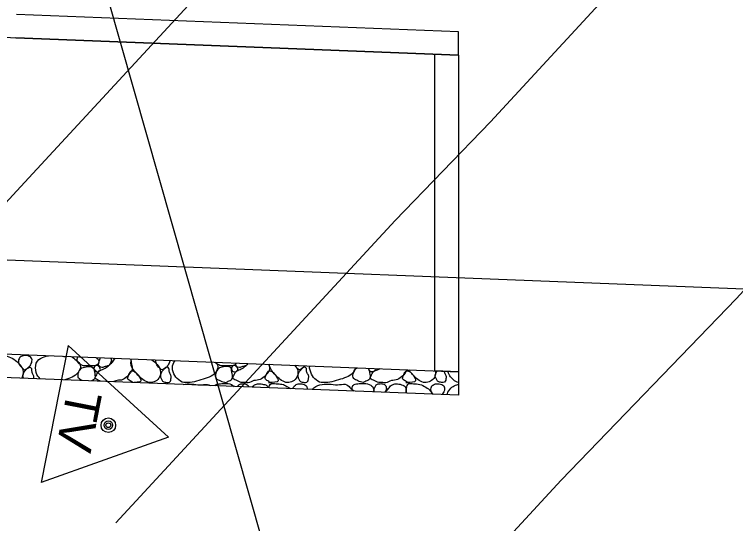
# Model space of a CAD drawing. Extents: x 1385284 to 1385995, y 1975154 to 1975620.
# Drawn here: x 1385575.03 to 1385605.82, y 1975429.75 to 1975451.48 of the extents above; entities that cross this region are included whole.
import ezdxf

# ---------------------------------------------------------------- set-up
doc = ezdxf.new("R2010")
doc.units = 0
for name, color, linetype in [('Default', 7, 'Continuous'), ('DTM CONTOURS_MAJOR', 7, 'Continuous'), ('DTM_CONTOURS_MINOR', 7, 'Continuous'), ('R_Proposed Const Limits', 7, 'Continuous'), ('R_Proposed Road', 7, 'Continuous'), ('S_SECONDARY_CTL', 7, 'Continuous')]:
    doc.layers.add(name, color=color, linetype=linetype)

msp = doc.modelspace()

# ---------------------------------------------------------------- linework, layer by layer
at = {"layer": 'Default'}
for p, q in [((1385568.987, 1975487.408), (1385600.804, 1975375.659)), ((1385593.986, 1975450.744), (1385575.124, 1975451.48)), ((1385593.986, 1975449.744), (1385593.986, 1975450.744)), ((1385593.986, 1975449.744), (1385575.085, 1975450.481)), ((1385575.085, 1975450.481), (1385593.986, 1975449.744)), ((1385592.986, 1975436.272), (1385592.986, 1975449.782)), ((1385592.986, 1975449.782), (1385593.986, 1975449.744)), ((1385593.986, 1975449.744), (1385593.986, 1975436.233)), ((1385574.559, 1975436.991), (1385593.986, 1975436.233)), ((1385592.986, 1975436.272), (1385593.986, 1975436.233)), ((1385593.986, 1975436.233), (1385592.986, 1975436.272)), ((1385593.986, 1975436.233), (1385593.986, 1975435.233)), ((1385593.986, 1975435.233), (1385574.52, 1975435.992))]:
    msp.add_line(p, q, dxfattribs=at)
msp.add_arc((1385575.884, 1975470.965), 20.5, 145.4884, 267.767, dxfattribs=at)
for points in [[(1385574.541, 1975435.991), (1385574.531, 1975436.001), (1385574.44, 1975436.091), (1385574.28, 1975436.257), (1385574.122, 1975436.498), (1385574.154, 1975436.724), (1385574.225, 1975436.966), (1385574.454, 1975436.913), (1385574.724, 1975436.919), (1385575.013, 1975436.774), (1385575.27, 1975436.563), (1385575.418, 1975436.303), (1385575.404, 1975436.06), (1385575.351, 1975435.979), (1385575.336, 1975435.96)], [(1385575.519, 1975436.344), (1385575.488, 1975436.27), (1385575.283, 1975436.452), (1385575.181, 1975436.63), (1385575.232, 1975436.85), (1385575.396, 1975436.923), (1385575.623, 1975436.93), (1385575.813, 1975436.805), (1385575.761, 1975436.567), (1385575.648, 1975436.402), (1385575.545, 1975436.355), (1385575.519, 1975436.344)], [(1385576.129, 1975435.929), (1385576.069, 1975435.99), (1385575.929, 1975436.165), (1385575.91, 1975436.641), (1385576.23, 1975436.871), (1385576.441, 1975436.91), (1385576.491, 1975436.915)], [(1385577.11, 1975436.891), (1385577.13, 1975436.89), (1385577.164, 1975436.887), (1385577.199, 1975436.887), (1385577.214, 1975436.887)], [(1385577.462, 1975436.878), (1385577.528, 1975436.853), (1385577.663, 1975436.729), (1385577.905, 1975436.536), (1385577.78, 1975436.176), (1385577.506, 1975435.992), (1385577.31, 1975435.925), (1385577.177, 1975435.888)], [(1385578.073, 1975436.49), (1385578.018, 1975436.467), (1385577.873, 1975436.524), (1385577.711, 1975436.611), (1385577.7, 1975436.767), (1385577.733, 1975436.841), (1385577.757, 1975436.866)], [(1385578.511, 1975436.837), (1385578.533, 1975436.82), (1385578.617, 1975436.757), (1385578.655, 1975436.649), (1385578.559, 1975436.482), (1385578.353, 1975436.49), (1385578.193, 1975436.484), (1385578.073, 1975436.49)], [(1385578.71, 1975435.828), (1385578.701, 1975435.833), (1385578.622, 1975435.877), (1385578.435, 1975435.935), (1385578.549, 1975436.104), (1385578.628, 1975436.29), (1385578.853, 1975436.335), (1385579.053, 1975436.493), (1385579.229, 1975436.634), (1385579.286, 1975436.762), (1385579.326, 1975436.805)], [(1385579.045, 1975436.49), (1385578.997, 1975436.476), (1385578.901, 1975436.452), (1385578.766, 1975436.399), (1385578.64, 1975436.44), (1385578.613, 1975436.547), (1385578.643, 1975436.661), (1385578.677, 1975436.762), (1385578.698, 1975436.813), (1385578.707, 1975436.829)], [(1385579.154, 1975436.812), (1385579.181, 1975436.756), (1385579.158, 1975436.637), (1385579.097, 1975436.52), (1385579.045, 1975436.49)], [(1385579.988, 1975436.779), (1385580.009, 1975436.721), (1385580.018, 1975436.568), (1385580.096, 1975436.284), (1385579.882, 1975436.076), (1385579.66, 1975435.854), (1385579.417, 1975435.882), (1385579.275, 1975435.82), (1385579.246, 1975435.807)], [(1385580.811, 1975435.77), (1385580.739, 1975435.767), (1385580.557, 1975435.852), (1385580.36, 1975436.034), (1385580.15, 1975436.257), (1385579.991, 1975436.498), (1385580.011, 1975436.684), (1385580.023, 1975436.765), (1385580.026, 1975436.778)], [(1385580.903, 1975436.743), (1385580.976, 1975436.693), (1385581.148, 1975436.543), (1385581.288, 1975436.303), (1385581.25, 1975435.986), (1385581.064, 1975435.814), (1385580.895, 1975435.77), (1385580.811, 1975435.77)], [(1385581.388, 1975436.344), (1385581.357, 1975436.27), (1385581.152, 1975436.452), (1385581.065, 1975436.612), (1385581.061, 1975436.714), (1385581.065, 1975436.737)], [(1385581.665, 1975436.714), (1385581.67, 1975436.675), (1385581.618, 1975436.549), (1385581.518, 1975436.402), (1385581.414, 1975436.355), (1385581.388, 1975436.344)], [(1385582.315, 1975435.774), (1385582.247, 1975435.74), (1385582.024, 1975435.878), (1385581.809, 1975436.123), (1385581.737, 1975436.512), (1385581.869, 1975436.673), (1385581.899, 1975436.705)], [(1385575.424, 1975435.956), (1385575.413, 1975435.978), (1385575.376, 1975436.038), (1385575.413, 1975436.183), (1385575.507, 1975436.295), (1385575.584, 1975436.384), (1385575.664, 1975436.44), (1385575.789, 1975436.388), (1385575.746, 1975436.271), (1385575.808, 1975436.146), (1385575.856, 1975436.024), (1385575.846, 1975435.955), (1385575.843, 1975435.94)], [(1385577.926, 1975435.859), (1385577.875, 1975435.881), (1385577.738, 1975435.937), (1385577.741, 1975436.149), (1385577.852, 1975436.394), (1385578.067, 1975436.444), (1385578.429, 1975436.473), (1385578.432, 1975436.232), (1385578.514, 1975435.921), (1385578.38, 1975435.869), (1385578.327, 1975435.843)], [(1385578.617, 1975436.224), (1385578.58, 1975436.225), (1385578.495, 1975436.222), (1385578.415, 1975436.304), (1385578.424, 1975436.422), (1385578.508, 1975436.524), (1385578.635, 1975436.474), (1385578.738, 1975436.313), (1385578.651, 1975436.254), (1385578.617, 1975436.224)], [(1385581.715, 1975435.875), (1385581.704, 1975435.851), (1385581.656, 1975435.761), (1385581.534, 1975435.775), (1385581.355, 1975435.794), (1385581.317, 1975435.911), (1385581.243, 1975436.019), (1385581.282, 1975436.183), (1385581.377, 1975436.295), (1385581.454, 1975436.384), (1385581.533, 1975436.44), (1385581.658, 1975436.388), (1385581.615, 1975436.271), (1385581.677, 1975436.146), (1385581.759, 1975436.009), (1385581.696, 1975435.906), (1385581.715, 1975435.875)], [(1385583.611, 1975436.638), (1385583.641, 1975436.602), (1385583.758, 1975436.477), (1385583.649, 1975436.176), (1385583.36, 1975435.986), (1385582.992, 1975435.885), (1385582.621, 1975435.757), (1385582.388, 1975435.771), (1385582.315, 1975435.774)], [(1385583.943, 1975436.49), (1385583.887, 1975436.467), (1385583.747, 1975436.523), (1385583.651, 1975436.585), (1385583.609, 1975436.638)], [(1385584.048, 1975435.77), (1385583.976, 1975435.781), (1385583.831, 1975435.85), (1385583.608, 1975435.92), (1385583.611, 1975436.149), (1385583.721, 1975436.394), (1385583.937, 1975436.444), (1385584.298, 1975436.473), (1385584.301, 1975436.232), (1385584.383, 1975435.92), (1385584.199, 1975435.843), (1385584.096, 1975435.795), (1385584.048, 1975435.77)], [(1385584.501, 1975436.603), (1385584.491, 1975436.562), (1385584.427, 1975436.482), (1385584.223, 1975436.49), (1385584.063, 1975436.484), (1385583.943, 1975436.49)], [(1385584.486, 1975436.224), (1385584.449, 1975436.225), (1385584.364, 1975436.222), (1385584.285, 1975436.304), (1385584.293, 1975436.422), (1385584.377, 1975436.524), (1385584.504, 1975436.474), (1385584.608, 1975436.313), (1385584.52, 1975436.254), (1385584.486, 1975436.224)], [(1385584.771, 1975435.77), (1385584.7, 1975435.766), (1385584.564, 1975435.846), (1385584.305, 1975435.935), (1385584.419, 1975436.104), (1385584.498, 1975436.29), (1385584.722, 1975436.335), (1385584.891, 1975436.467), (1385584.978, 1975436.552), (1385585.01, 1975436.583)], [(1385584.914, 1975436.49), (1385584.867, 1975436.476), (1385584.771, 1975436.452), (1385584.636, 1975436.399), (1385584.509, 1975436.44), (1385584.481, 1975436.525), (1385584.491, 1975436.577), (1385584.497, 1975436.603)], [(1385585.899, 1975436.549), (1385585.915, 1975436.47), (1385585.952, 1975436.271), (1385585.751, 1975436.076), (1385585.529, 1975435.854), (1385585.253, 1975435.887), (1385585.016, 1975435.711), (1385584.85, 1975435.791), (1385584.771, 1975435.77)], [(1385584.998, 1975436.584), (1385584.977, 1975436.546), (1385584.951, 1975436.511), (1385584.914, 1975436.49)], [(1385586.68, 1975435.77), (1385586.609, 1975435.767), (1385586.426, 1975435.852), (1385586.229, 1975436.034), (1385586.019, 1975436.257), (1385585.922, 1975436.447), (1385585.89, 1975436.546), (1385585.889, 1975436.549)], [(1385587.011, 1975436.505), (1385587.07, 1975436.42), (1385587.156, 1975436.279), (1385587.119, 1975435.986), (1385586.933, 1975435.814), (1385586.765, 1975435.77), (1385586.68, 1975435.77)], [(1385587.258, 1975436.344), (1385587.226, 1975436.27), (1385587.078, 1975436.399), (1385587.014, 1975436.488), (1385587.002, 1975436.506)], [(1385587.584, 1975435.875), (1385587.574, 1975435.851), (1385587.525, 1975435.761), (1385587.403, 1975435.775), (1385587.224, 1975435.794), (1385587.187, 1975435.911), (1385587.112, 1975436.019), (1385587.151, 1975436.183), (1385587.246, 1975436.295), (1385587.323, 1975436.384), (1385587.403, 1975436.44), (1385587.527, 1975436.388), (1385587.485, 1975436.271), (1385587.546, 1975436.146), (1385587.629, 1975436.009), (1385587.565, 1975435.906), (1385587.584, 1975435.875)], [(1385587.438, 1975436.489), (1385587.407, 1975436.449), (1385587.348, 1975436.385), (1385587.283, 1975436.355), (1385587.258, 1975436.344)], [(1385588.184, 1975435.774), (1385588.117, 1975435.74), (1385587.894, 1975435.878), (1385587.706, 1975436.096), (1385587.621, 1975436.364), (1385587.639, 1975436.481)], [(1385589.58, 1975436.405), (1385589.576, 1975436.319), (1385589.488, 1975436.149), (1385589.23, 1975435.986), (1385588.861, 1975435.885), (1385588.49, 1975435.757), (1385588.257, 1975435.771), (1385588.184, 1975435.774)], [(1385589.917, 1975435.77), (1385589.845, 1975435.781), (1385589.701, 1975435.85), (1385589.477, 1975435.92), (1385589.48, 1975436.149), (1385589.551, 1975436.322), (1385589.646, 1975436.387), (1385589.673, 1975436.401)], [(1385590.15, 1975436.383), (1385590.181, 1975436.327), (1385590.188, 1975436.197), (1385590.252, 1975435.92), (1385590.068, 1975435.843), (1385589.965, 1975435.795), (1385589.917, 1975435.77)], [(1385590.356, 1975436.224), (1385590.318, 1975436.225), (1385590.234, 1975436.222), (1385590.166, 1975436.296), (1385590.156, 1975436.358), (1385590.159, 1975436.383)], [(1385590.641, 1975435.77), (1385590.569, 1975435.766), (1385590.434, 1975435.846), (1385590.174, 1975435.935), (1385590.288, 1975436.104), (1385590.367, 1975436.29), (1385590.539, 1975436.296), (1385590.621, 1975436.358), (1385590.629, 1975436.364)], [(1385590.46, 1975436.371), (1385590.473, 1975436.348), (1385590.451, 1975436.295), (1385590.389, 1975436.254), (1385590.356, 1975436.224)], [(1385580.1, 1975435.774), (1385580.061, 1975435.784), (1385579.975, 1975435.849), (1385579.822, 1975435.935), (1385579.931, 1975436.121), (1385579.979, 1975436.285), (1385580.16, 1975436.259), (1385580.28, 1975436.155), (1385580.347, 1975436.01), (1385580.519, 1975435.773), (1385580.188, 1975435.778), (1385580.138, 1975435.773)], [(1385585.998, 1975435.77), (1385585.95, 1975435.77), (1385585.854, 1975435.842), (1385585.691, 1975435.935), (1385585.8, 1975436.121), (1385585.848, 1975436.285), (1385586.029, 1975436.259), (1385586.149, 1975436.155), (1385586.216, 1975436.01), (1385586.403, 1975435.762), (1385585.653, 1975435.779), (1385586.04, 1975435.768), (1385586.031, 1975435.77)], [(1385591.785, 1975436.319), (1385591.785, 1975436.317), (1385591.763, 1975436.215), (1385591.62, 1975436.076), (1385591.398, 1975435.854), (1385591.122, 1975435.887), (1385590.885, 1975435.711), (1385590.72, 1975435.791), (1385590.641, 1975435.77)], [(1385591.867, 1975435.77), (1385591.819, 1975435.77), (1385591.723, 1975435.842), (1385591.561, 1975435.935), (1385591.67, 1975436.121), (1385591.717, 1975436.285), (1385591.899, 1975436.259), (1385592.018, 1975436.155), (1385592.085, 1975436.01), (1385592.272, 1975435.762), (1385591.523, 1975435.779), (1385591.909, 1975435.768), (1385591.901, 1975435.77)], [(1385592.549, 1975435.77), (1385592.478, 1975435.767), (1385592.295, 1975435.852), (1385592.099, 1975436.034), (1385591.955, 1975436.195), (1385591.88, 1975436.301), (1385591.871, 1975436.316)], [(1385592.992, 1975436.272), (1385592.996, 1975436.26), (1385593.023, 1975436.183), (1385592.988, 1975435.986), (1385592.802, 1975435.814), (1385592.634, 1975435.77), (1385592.549, 1975435.77)], [(1385593.453, 1975435.875), (1385593.443, 1975435.851), (1385593.395, 1975435.761), (1385593.272, 1975435.775), (1385593.094, 1975435.794), (1385593.056, 1975435.911), (1385592.982, 1975436.019), (1385593.012, 1975436.164), (1385593.064, 1975436.236), (1385593.091, 1975436.268)], [(1385593.365, 1975436.258), (1385593.383, 1975436.216), (1385593.42, 1975436.127), (1385593.498, 1975436.009), (1385593.434, 1975435.906), (1385593.453, 1975435.875)], [(1385593.986, 1975435.766), (1385593.93, 1975435.775), (1385593.749, 1975435.896), (1385593.621, 1975436.051), (1385593.549, 1975436.208), (1385593.535, 1975436.251)], [(1385583.606, 1975435.637), (1385583.618, 1975435.656), (1385583.669, 1975435.706), (1385583.866, 1975435.724), (1385584.151, 1975435.752), (1385584.345, 1975435.667), (1385584.414, 1975435.606)], [(1385585.89, 1975435.548), (1385585.9, 1975435.607), (1385585.967, 1975435.762), (1385586.193, 1975435.71), (1385586.463, 1975435.716), (1385586.676, 1975435.607), (1385586.782, 1975435.535), (1385586.811, 1975435.512)], [(1385589.503, 1975435.407), (1385589.492, 1975435.419), (1385589.444, 1975435.466), (1385589.439, 1975435.574), (1385589.516, 1975435.706), (1385589.736, 1975435.724), (1385590.035, 1975435.754), (1385590.334, 1975435.632), (1385590.385, 1975435.455), (1385590.366, 1975435.384), (1385590.362, 1975435.374)], [(1385591.768, 1975435.319), (1385591.766, 1975435.325), (1385591.739, 1975435.394), (1385591.762, 1975435.521), (1385591.833, 1975435.763), (1385592.062, 1975435.71), (1385592.332, 1975435.716), (1385592.621, 1975435.571), (1385592.794, 1975435.426), (1385592.881, 1975435.304), (1385592.899, 1975435.275)], [(1385582.234, 1975435.691), (1385582.334, 1975435.713), (1385582.602, 1975435.721), (1385582.953, 1975435.65), (1385583.252, 1975435.715), (1385583.356, 1975435.666), (1385583.385, 1975435.646)], [(1385584.564, 1975435.6), (1385584.577, 1975435.631), (1385584.625, 1975435.71), (1385584.767, 1975435.726), (1385584.939, 1975435.722), (1385585.014, 1975435.634), (1385585.031, 1975435.591), (1385585.034, 1975435.582)], [(1385585.173, 1975435.576), (1385585.182, 1975435.588), (1385585.24, 1975435.655), (1385585.408, 1975435.731), (1385585.624, 1975435.706), (1385585.822, 1975435.665), (1385585.857, 1975435.583), (1385585.866, 1975435.549)], [(1385586.932, 1975435.508), (1385586.933, 1975435.542), (1385586.982, 1975435.652), (1385587.134, 1975435.72), (1385587.362, 1975435.727), (1385587.515, 1975435.618), (1385587.537, 1975435.516), (1385587.536, 1975435.484)], [(1385587.745, 1975435.476), (1385587.835, 1975435.578), (1385588.057, 1975435.697), (1385588.463, 1975435.722), (1385588.822, 1975435.65), (1385589.188, 1975435.743), (1385589.36, 1975435.561), (1385589.467, 1975435.453), (1385589.502, 1975435.407)], [(1385590.361, 1975435.374), (1385590.367, 1975435.405), (1385590.387, 1975435.475), (1385590.425, 1975435.585), (1385590.486, 1975435.709), (1385590.636, 1975435.726), (1385590.808, 1975435.722), (1385590.921, 1975435.594), (1385590.908, 1975435.461), (1385590.867, 1975435.379), (1385590.851, 1975435.355)], [(1385590.853, 1975435.355), (1385590.891, 1975435.392), (1385590.984, 1975435.462), (1385591.066, 1975435.638), (1385591.277, 1975435.731), (1385591.493, 1975435.706), (1385591.756, 1975435.62), (1385591.744, 1975435.458), (1385591.769, 1975435.345), (1385591.774, 1975435.319)], [(1385592.89, 1975435.275), (1385592.845, 1975435.338), (1385592.79, 1975435.438), (1385592.84, 1975435.647), (1385593.004, 1975435.72), (1385593.231, 1975435.727), (1385593.421, 1975435.602), (1385593.386, 1975435.4), (1385593.324, 1975435.303), (1385593.286, 1975435.26)], [(1385593.505, 1975435.251), (1385593.509, 1975435.305), (1385593.608, 1975435.507), (1385593.8, 1975435.651), (1385593.974, 1975435.691), (1385593.986, 1975435.694)]]:
    msp.add_open_spline(points, degree=3, dxfattribs=at)
at = {"layer": 'DTM CONTOURS_MAJOR'}
msp.add_lwpolyline([(1385567.349, 1975435.532), (1385575.643, 1975444.505), (1385584.2, 1975453.764), (1385584.866, 1975454.455), (1385593.445, 1975463.74), (1385594.049, 1975464.365), (1385602.648, 1975473.677), (1385603.227, 1975473.83), (1385603.894, 1975475.512), (1385603.308, 1975476.333), (1385604.191, 1975491.234), (1385600.884, 1975493.495), (1385599.902, 1975506.35), (1385595.893, 1975509.526), (1385591.739, 1975515.976)], dxfattribs=at)
at = {"layer": 'DTM_CONTOURS_MINOR'}
for points in [[(1385579.367, 1975429.786), (1385585.057, 1975435.943), (1385591.289, 1975442.686), (1385595.354, 1975446.898), (1385601.553, 1975453.608), (1385605.67, 1975457.865), (1385611.834, 1975464.54), (1385616.326, 1975465.731), (1385621.494, 1975478.78), (1385616.95, 1975485.142), (1385617.369, 1975492.225), (1385607.301, 1975499.112)], [(1385588.091, 1975420.679), (1385590.613, 1975423.205), (1385594.472, 1975427.38), (1385598.378, 1975431.607), (1385605.841, 1975439.341), (1385609.662, 1975443.476), (1385617.29, 1975451.365), (1385621.019, 1975455.403), (1385629.424, 1975457.631), (1385639.095, 1975482.048), (1385634.346, 1975488.696), (1385629.707, 1975493.323), (1385629.373, 1975493.57), (1385625.229, 1975496.854)]]:
    msp.add_lwpolyline(points, dxfattribs=at)
at = {"layer": 'R_Proposed Const Limits'}
msp.add_line((1385645.491, 1975438.228), (1385574.715, 1975440.988), dxfattribs=at)
at = {"layer": 'R_Proposed Road'}
msp.add_arc((1385514.357, 1974795.066), 683.494, 77.498258, 106.910819, dxfattribs=at)
at = {"layer": 'S_SECONDARY_CTL'}
for p, q in [((1385577.32, 1975437.353), (1385576.175, 1975431.507)), ((1385581.603, 1975433.447), (1385577.32, 1975437.353)), ((1385581.603, 1975433.447), (1385576.175, 1975431.507))]:
    msp.add_line(p, q, dxfattribs=at)
for radius in [0.311, 0.183, 0.103]:
    msp.add_circle((1385579.041, 1975433.949), radius, dxfattribs=at)

# ---------------------------------------------------------------- texts
msp.add_text('TV', height=1.5, rotation=258.9164, dxfattribs=at).set_placement((1385577.299, 1975435.517))

doc.saveas('drawing.dxf')
